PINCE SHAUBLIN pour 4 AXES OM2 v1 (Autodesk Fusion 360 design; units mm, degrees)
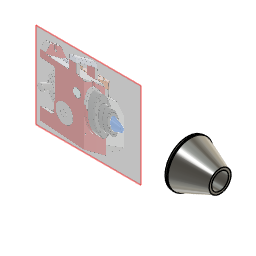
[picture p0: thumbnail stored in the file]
sketch "Esquisse" plane through (0, 0, 0) normal (0, 0, 1) x axis (1, 0, 0)
  line L1 (0, 15.875) -> (0, 0)
  line L2 (67.755, 15.875) -> (0, 15.875)
  line L3 (83.3, 18.7) -> (67.755, 15.875)
  line L4 (84.3, 18.7) -> (83.3, 18.7)
  line L5 (108.7, 9) -> (84.3, 18.7)
  line L6 (108.7, 0) -> (108.7, 9)
  line L7 (0, 0) -> (108.7, 0)
  point P1 (0, 0)
  point P2 (0, 0)
  point P9 (0, 0)
  point P5 (83.3, 18.7)
  point P6 (84.3, 18.7)
  point P7 (108.7, 9)
  point P8 (108.7, 0)
  coincident P1 P2
  vertical L1
  perpendicular L1 L2
  perpendicular L1 L4
  perpendicular L4 L6
  coincident P1 P9
  perpendicular L1 L7
  dimension "d1" distance L1 L6 = 108.7
  dimension "d2" distance L2 L7 = 15.875 (= "31.75 mm / 2")
  dimension "d3" distance L4 L7 = 18.7 (= "( 37.4 / 2 ) * 1 mm")
  dimension "d4" distance P5 L6 = 25.4
  dimension "d5" angle L2 L3 = 10.3 (= "Angular Dimension-2")
  dimension "d6" distance P5 P6 = 1
  dimension "d7" distance P7 P8 = 9
revolve "Révolution" sketch "Esquisse"
hole "Perçage" HoleDepth 108.7 HoleDiameter 14
base_feature "Fonction de base1"
base_feature "Fonction de base1"
base_feature "Fonction de base1"
position "Position1"
work_plane "Plan de construction" AlongDistance 0
remove_instance "RemoveInstance1"
split "Scinder"
remove_body "RemoveBody1"
canvas "Canevas"
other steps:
create_component "CreateComponent1"
create_component "CreateComponent2"
create_component "CreateComponent3"
create_component "CreateComponent1"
